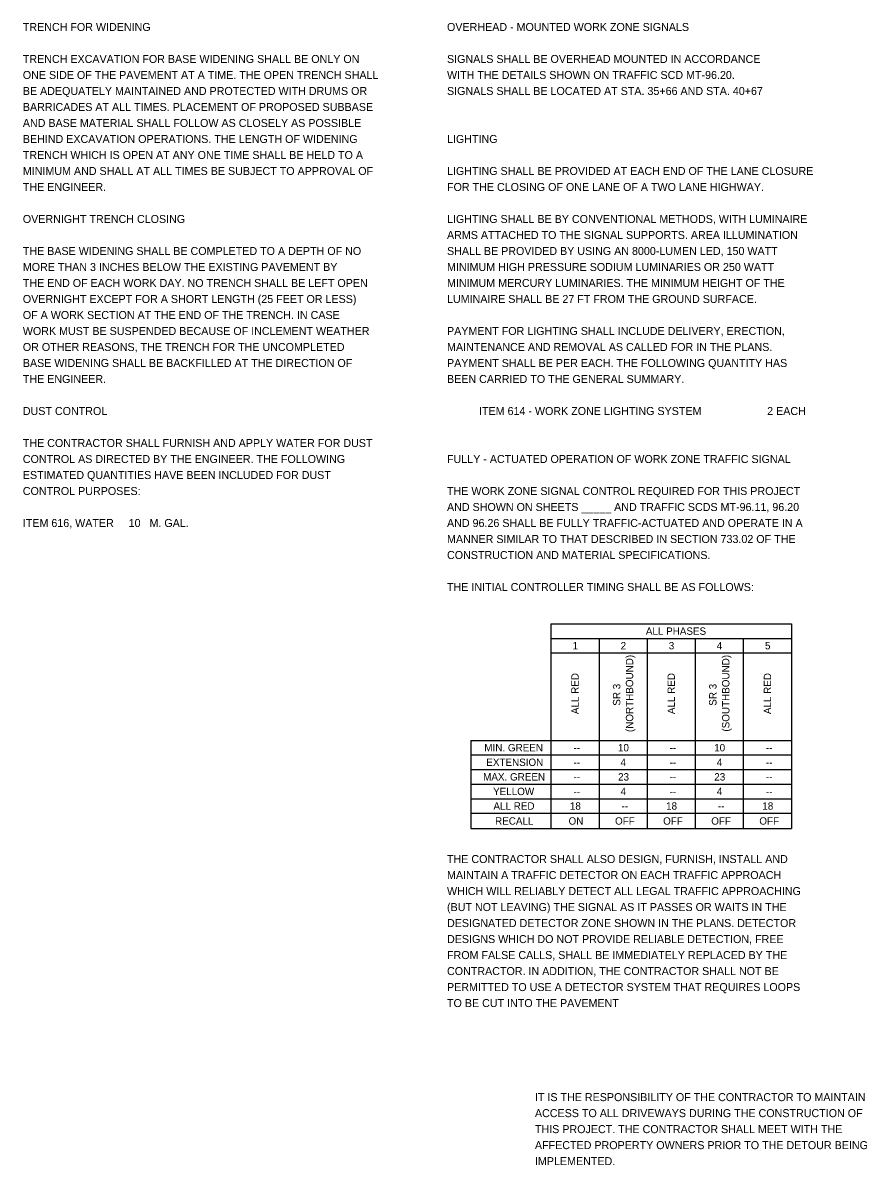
# Model space of a CAD drawing. Extents: x -32.3 to 34, y 0 to 22.
# Drawn here: x -17.5 to -2.74, y 1.15 to 21.14 of the extents above; entities that cross this region are included whole.
import ezdxf

# ---------------------------------------------------------------- set-up
doc = ezdxf.new("R2010")
doc.units = 0
doc.layers.add('Default', color=7, linetype='Continuous')
doc.layers.add('SH_Text', color=7, linetype='Continuous')

msp = doc.modelspace()

# ---------------------------------------------------------------- linework, layer by layer
at = {"layer": 'SH_Text'}
for p, q in [((-8.268, 10.626), (-4.06, 10.626)), ((-8.268, 10.626), (-8.268, 7.043)), ((-4.06, 10.626), (-4.06, 7.043)), ((-8.268, 10.371), (-4.06, 10.371)), ((-7.426, 10.371), (-7.426, 7.043)), ((-6.585, 10.371), (-6.585, 7.043)), ((-5.743, 10.371), (-5.743, 7.043)), ((-4.902, 10.371), (-4.902, 10.116)), ((-8.268, 10.116), (-4.06, 10.116)), ((-4.902, 10.116), (-4.902, 8.586)), ((-9.67, 8.586), (-4.06, 8.586)), ((-9.67, 8.586), (-9.67, 7.043)), ((-4.902, 8.586), (-4.902, 7.043)), ((-9.67, 8.331), (-4.06, 8.331)), ((-9.67, 8.076), (-4.06, 8.076)), ((-9.67, 7.821), (-4.06, 7.821)), ((-9.67, 7.566), (-4.06, 7.566)), ((-9.67, 7.311), (-4.06, 7.311)), ((-9.67, 7.043), (-4.06, 7.043))]:
    msp.add_line(p, q, dxfattribs=at)

# ---------------------------------------------------------------- texts
at = {"layer": 'Default'}
for s, p in [('TRENCH EXCAVATION FOR BASE WIDENING SHALL BE ONLY ON', (-17.505, 20.44)), ('SIGNALS SHALL BE OVERHEAD MOUNTED IN ACCORDANCE', (-10.085, 20.44)), ('ONE SIDE OF THE PAVEMENT AT A TIME. THE OPEN TRENCH SHALL', (-17.505, 20.16)), ('WITH THE DETAILS SHOWN ON TRAFFIC SCD MT-96.20.', (-10.085, 20.16)), ('BE ADEQUATELY MAINTAINED AND PROTECTED WITH DRUMS OR', (-17.505, 19.88)), ('SIGNALS SHALL BE LOCATED AT STA. 35+66 AND STA. 40+67', (-10.085, 19.88)), ('BARRICADES AT ALL TIMES. PLACEMENT OF PROPOSED SUBBASE', (-17.505, 19.6)), ('AND BASE MATERIAL SHALL FOLLOW AS CLOSELY AS POSSIBLE', (-17.505, 19.32)), ('BEHIND EXCAVATION OPERATIONS. THE LENGTH OF WIDENING', (-17.505, 19.04)), ('TRENCH WHICH IS OPEN AT ANY ONE TIME SHALL BE HELD TO A', (-17.505, 18.76)), ('MINIMUM AND SHALL AT ALL TIMES BE SUBJECT TO APPROVAL OF', (-17.505, 18.48)), ('LIGHTING SHALL BE PROVIDED AT EACH END OF THE LANE CLOSURE ', (-10.085, 18.48)), ('THE ENGINEER.', (-17.505, 18.2)), ('FOR THE CLOSING OF ONE LANE OF A TWO LANE HIGHWAY.', (-10.085, 18.2)), ('LIGHTING SHALL BE BY CONVENTIONAL METHODS, WITH LUMINAIRE ', (-10.085, 17.64)), ('ARMS ATTACHED TO THE SIGNAL SUPPORTS. AREA ILLUMINATION ', (-10.085, 17.36)), ('THE BASE WIDENING SHALL BE COMPLETED TO A DEPTH OF NO', (-17.505, 17.08)), ('SHALL BE PROVIDED BY USING AN 8000-LUMEN LED, 150 WATT ', (-10.085, 17.08)), ('MORE THAN 3 INCHES BELOW THE EXISTING PAVEMENT BY', (-17.505, 16.8)), ('MINIMUM HIGH PRESSURE SODIUM LUMINARIES OR 250 WATT ', (-10.085, 16.8)), ('THE END OF EACH WORK DAY. NO TRENCH SHALL BE LEFT OPEN', (-17.505, 16.52)), ('MINIMUM MERCURY LUMINARIES. THE MINIMUM HEIGHT OF THE ', (-10.085, 16.52)), ('OVERNIGHT EXCEPT FOR A SHORT LENGTH (25 FEET OR LESS)', (-17.505, 16.24)), ('LUMINAIRE SHALL BE 27 FT FROM THE GROUND SURFACE.  ', (-10.085, 16.24)), ('OF A WORK SECTION AT THE END OF THE TRENCH. IN CASE', (-17.505, 15.96)), ('WORK MUST BE SUSPENDED BECAUSE OF INCLEMENT WEATHER', (-17.505, 15.68)), ('PAYMENT FOR LIGHTING SHALL INCLUDE DELIVERY, ERECTION, ', (-10.085, 15.68)), ('OR OTHER REASONS, THE TRENCH FOR THE UNCOMPLETED', (-17.505, 15.4)), ('MAINTENANCE AND REMOVAL AS CALLED FOR IN THE PLANS. ', (-10.085, 15.4)), ('BASE WIDENING SHALL BE BACKFILLED AT THE DIRECTION OF', (-17.505, 15.12)), ('PAYMENT SHALL BE PER EACH. THE FOLLOWING QUANTITY HAS ', (-10.085, 15.12)), ('THE ENGINEER.', (-17.505, 14.84)), ('BEEN CARRIED TO THE GENERAL SUMMARY.', (-10.085, 14.84)), ('ITEM 614 - WORK ZONE LIGHTING SYSTEM ', (-9.525, 14.28)), ('2 EACH', (-4.485, 14.28)), ('THE CONTRACTOR SHALL FURNISH AND APPLY WATER FOR DUST', (-17.505, 13.72)), ('CONTROL AS DIRECTED BY THE ENGINEER. THE FOLLOWING', (-17.505, 13.44)), ('ESTIMATED QUANTITIES HAVE BEEN INCLUDED FOR DUST', (-17.505, 13.16)), ('CONTROL PURPOSES:', (-17.505, 12.88)), ('THE WORK ZONE SIGNAL CONTROL REQUIRED FOR THIS PROJECT ', (-10.085, 12.88)), ('AND SHOWN ON SHEETS _____ AND TRAFFIC SCDS MT-96.11, 96.20 ', (-10.085, 12.6)), ('ITEM 616, WATER     10   M. GAL.', (-17.505, 12.32)), ('AND 96.26 SHALL BE FULLY TRAFFIC-ACTUATED AND OPERATE IN A ', (-10.085, 12.32)), ('MANNER SIMILAR TO THAT DESCRIBED IN SECTION 733.02 OF THE ', (-10.085, 12.04)), ('CONSTRUCTION AND MATERIAL SPECIFICATIONS.', (-10.085, 11.76)), ('THE INITIAL CONTROLLER TIMING SHALL BE AS FOLLOWS:', (-10.085, 11.2)), ('THE CONTRACTOR SHALL ALSO DESIGN, FURNISH, INSTALL AND ', (-10.085, 6.44)), ('MAINTAIN A TRAFFIC DETECTOR ON EACH TRAFFIC APPROACH ', (-10.085, 6.16)), ('WHICH WILL RELIABLY DETECT ALL LEGAL TRAFFIC APPROACHING ', (-10.085, 5.88)), ('(BUT NOT LEAVING) THE SIGNAL AS IT PASSES OR WAITS IN THE ', (-10.085, 5.6)), ('DESIGNATED DETECTOR ZONE SHOWN IN THE PLANS. DETECTOR ', (-10.085, 5.32)), ('DESIGNS WHICH DO NOT PROVIDE RELIABLE DETECTION, FREE ', (-10.085, 5.04)), ('FROM FALSE CALLS, SHALL BE IMMEDIATELY REPLACED BY THE ', (-10.085, 4.76)), ('CONTRACTOR. IN ADDITION, THE CONTRACTOR SHALL NOT BE ', (-10.085, 4.48)), ('PERMITTED TO USE A DETECTOR SYSTEM THAT REQUIRES LOOPS ', (-10.085, 4.2)), ('TO BE CUT INTO THE PAVEMENT', (-10.085, 3.92))]:
    msp.add_text(s, height=0.14, dxfattribs=at).set_placement(p)
at = {"layer": 'SH_Text'}
for s, height, p in [('TRENCH FOR WIDENING', 0.14, (-17.505, 21)), ('OVERHEAD - MOUNTED WORK ZONE SIGNALS', 0.14, (-10.085, 21)), ('LIGHTING', 0.14, (-10.085, 19.04)), ('OVERNIGHT TRENCH CLOSING', 0.14, (-17.505, 17.64)), ('DUST CONTROL', 0.14, (-17.505, 14.28)), ('FULLY - ACTUATED OPERATION OF WORK ZONE TRAFFIC SIGNAL', 0.14, (-10.085, 13.44)), ('ALL PHASES', 0.129, (-6.607, 10.434)), ('1', 0.129, (-7.889, 10.179)), ('2', 0.129, (-7.048, 10.179)), ('3', 0.129, (-6.206, 10.179)), ('4', 0.129, (-5.367, 10.179)), ('5', 0.129, (-4.523, 10.179)), ('MIN. GREEN', 0.129, (-9.432, 8.394)), (' --', 0.129, (-7.921, 8.394)), ('10', 0.129, (-7.095, 8.394)), (' --', 0.129, (-6.238, 8.394)), ('10', 0.129, (-5.412, 8.394)), (' --', 0.129, (-4.555, 8.394)), ('EXTENSION', 0.129, (-9.398, 8.139)), (' --', 0.129, (-7.921, 8.139)), ('4', 0.129, (-7.049, 8.139)), (' --', 0.129, (-6.238, 8.139)), ('4', 0.129, (-5.366, 8.139)), (' --', 0.129, (-4.555, 8.139)), ('MAX. GREEN', 0.129, (-9.453, 7.884)), ('23', 0.129, (-7.093, 7.884)), ('23', 0.129, (-5.41, 7.884)), (' --', 0.129, (-7.921, 7.884)), (' --', 0.129, (-6.238, 7.884)), (' --', 0.129, (-4.555, 7.884)), ('YELLOW', 0.129, (-9.279, 7.629)), (' --', 0.129, (-7.921, 7.629)), ('4', 0.129, (-7.049, 7.629)), (' --', 0.129, (-6.238, 7.629)), ('4', 0.129, (-5.366, 7.629)), (' --', 0.129, (-4.555, 7.629)), ('ALL RED', 0.129, (-9.273, 7.374)), ('18', 0.129, (-7.936, 7.374)), (' --', 0.129, (-7.079, 7.374)), ('18', 0.129, (-6.253, 7.374)), (' --', 0.129, (-5.396, 7.374)), ('18', 0.129, (-4.57, 7.374)), ('RECALL', 0.129, (-9.244, 7.112)), ('ON', 0.129, (-7.959, 7.112)), ('OFF', 0.129, (-7.146, 7.112)), ('OFF', 0.129, (-6.305, 7.112)), ('OFF', 0.129, (-5.463, 7.112)), ('OFF', 0.129, (-4.622, 7.112)), ('IT IS THE RESPONSIBILITY OF THE CONTRACTOR TO MAINTAIN ', 0.14, (-8.547, 2.274)), ('ACCESS TO ALL DRIVEWAYS DURING THE CONSTRUCTION OF ', 0.14, (-8.547, 1.994)), ('THIS PROJECT. THE CONTRACTOR SHALL MEET WITH THE ', 0.14, (-8.547, 1.714)), ('AFFECTED PROPERTY OWNERS PRIOR TO THE DETOUR BEING ', 0.14, (-8.547, 1.434)), ('IMPLEMENTED.', 0.14, (-8.547, 1.154))]:
    msp.add_text(s, height=height, dxfattribs=at).set_placement(p)
for s, height, p in [('(NORTHBOUND)', 0.12903, (-6.828, 8.732)), ('(SOUTHBOUND)', 0.12903, (-5.145, 8.74)), ('ALL RED', 0.129, (-7.782, 9.046)), ('ALL RED', 0.129, (-6.099, 9.046)), ('ALL RED', 0.129, (-4.416, 9.046)), ('SR 3', 0.129, (-7.054, 9.193)), ('SR 3', 0.129, (-5.371, 9.193))]:
    msp.add_text(s, height=height, rotation=90, dxfattribs=at).set_placement(p)

doc.saveas('drawing.dxf')
